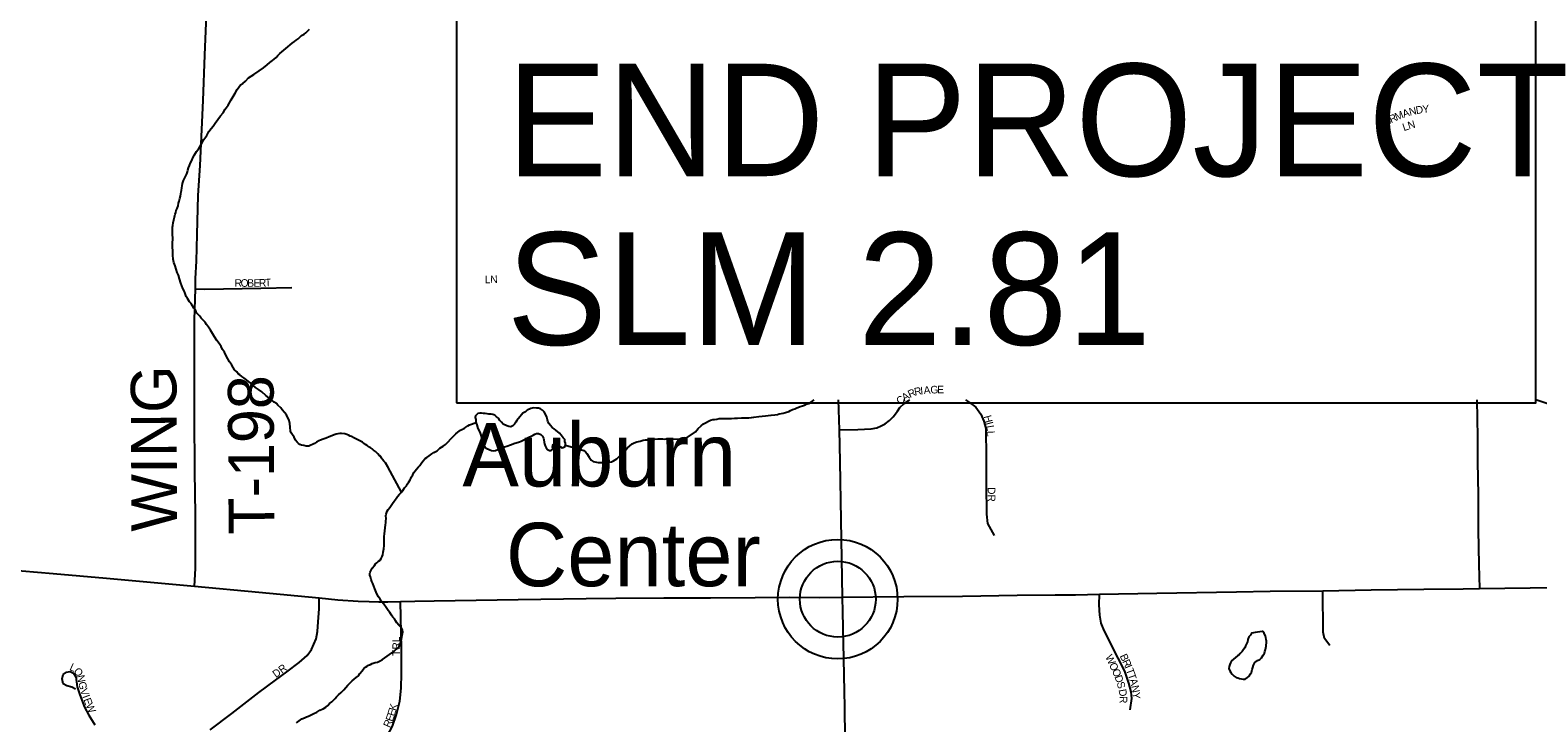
# Model space of a CAD drawing. Extents: x -10.1 to 68, y -9.5 to 29.2.
# Drawn here: x 2.607 to 4.482, y 19.418 to 20.28 of the extents above; entities that cross this region are included whole.
import ezdxf

# ---------------------------------------------------------------- set-up
doc = ezdxf.new("R2010")
doc.units = 0
for name, color, linetype in [('GM_X_County_Road', 7, 'Continuous'), ('GM_X_Minor_Lake', 7, 'Continuous'), ('GM_X_Minor_River', 7, 'Continuous'), ('GM_X_Township_Road', 7, 'Continuous'), ('GM_X_Township_Road_Text', 7, 'Continuous'), ('GM_X_Township_Subdivision', 7, 'Continuous'), ('GM_X_Township_Subdivision_Text', 7, 'Continuous'), ('GM_X_Unincorporated', 7, 'Continuous'), ('GM_X_Unincorporated_Text', 7, 'Continuous'), ('SH_Text', 7, 'Continuous')]:
    doc.layers.add(name, color=color, linetype=linetype)

msp = doc.modelspace()

# ---------------------------------------------------------------- linework, layer by layer
at = {"layer": 'GM_X_County_Road'}
for points in [[(3.6118, 19.82), (3.6127, 19.7829), (3.6136, 19.7433), (3.6149, 19.6704), (3.6165, 19.5745)], [(4.4061, 19.82), (4.4069, 19.7738), (4.4069, 19.743), (4.4076, 19.7017), (4.4079, 19.6581), (4.4086, 19.6153), (4.4092, 19.5855)], [(2.5767, 19.6089), (2.6354, 19.6041), (2.7015, 19.5982), (2.8112, 19.5881), (2.8911, 19.5808), (2.9659, 19.5737), (2.9895, 19.5713), (3.0145, 19.5694), (3.0284, 19.569), (3.0405, 19.5687), (3.0513, 19.5687), (3.0671, 19.5692), (3.0851, 19.5694), (3.1093, 19.5698), (3.2135, 19.5718), (3.2981, 19.5727), (3.335, 19.5733), (3.3949, 19.5737), (3.4527, 19.5735), (3.5085, 19.5739), (3.5513, 19.5743), (3.5884, 19.5741), (3.6165, 19.5745), (3.6934, 19.5753), (3.7664, 19.5759), (3.8343, 19.5769), (3.8817, 19.5774), (3.9069, 19.5776), (3.9366, 19.5781), (4.0079, 19.5793), (4.1072, 19.5811), (4.1489, 19.582), (4.2146, 19.5825), (4.2746, 19.5835), (4.3403, 19.5845), (4.3891, 19.5847), (4.4092, 19.5855), (4.5666, 19.5872)], [(3.6165, 19.5745), (3.6171, 19.5562), (3.6182, 19.4976), (3.619, 19.4571)], [(3.619, 19.4571), (3.6194, 19.4382), (3.62, 19.3984)]]:
    msp.add_lwpolyline(points, dxfattribs=at)
at = {"layer": 'GM_X_Minor_Lake'}
for points in [[(3.2548, 19.757), (3.2571, 19.7593), (3.2563, 19.7616), (3.2571, 19.7646), (3.2594, 19.765), (3.2616, 19.7646), (3.2662, 19.7616), (3.2684, 19.7604), (3.2715, 19.7616), (3.2726, 19.7638), (3.2726, 19.7661), (3.2718, 19.7684), (3.2715, 19.7707), (3.2696, 19.7729), (3.2673, 19.776), (3.265, 19.7786), (3.2605, 19.7824), (3.2582, 19.7839), (3.256, 19.7858), (3.2537, 19.7881), (3.2522, 19.7904), (3.2507, 19.793), (3.2499, 19.7953), (3.2492, 19.7984), (3.2484, 19.8006), (3.2461, 19.8052), (3.2439, 19.8071), (3.2412, 19.809), (3.239, 19.8097), (3.2363, 19.8097), (3.2325, 19.8101), (3.2295, 19.8094), (3.2249, 19.8071), (3.2227, 19.8052), (3.2195, 19.8034)], [(3.209, 19.7897), (3.2068, 19.7878), (3.2045, 19.7866), (3.2022, 19.787), (3.1996, 19.7878), (3.195, 19.79), (3.1928, 19.7923), (3.1909, 19.7946), (3.189, 19.7972), (3.1867, 19.7991), (3.1844, 19.801), (3.1822, 19.8018), (3.1799, 19.8022), (3.1772, 19.8022), (3.175, 19.8026), (3.1727, 19.8033), (3.1704, 19.8033), (3.1682, 19.8037), (3.1659, 19.8037), (3.1636, 19.803), (3.1606, 19.8003), (3.1602, 19.798), (3.161, 19.7957), (3.161, 19.7935), (3.1613, 19.7912), (3.1621, 19.7889), (3.1636, 19.7844), (3.1659, 19.7798), (3.1666, 19.7772), (3.1696, 19.768), (3.1708, 19.7654), (3.1715, 19.7627), (3.1738, 19.7601), (3.1783, 19.7578), (3.1806, 19.757), (3.1829, 19.7567), (3.1855, 19.757), (3.1882, 19.7582), (3.1904, 19.7586), (3.1931, 19.7597), (3.1954, 19.7612), (3.2007, 19.7627), (3.2029, 19.7639), (3.2052, 19.7646), (3.2082, 19.7658), (3.2151, 19.768), (3.2173, 19.7688), (3.22, 19.7699), (3.2253, 19.773), (3.2276, 19.7741), (3.2298, 19.7748), (3.2321, 19.776), (3.2344, 19.7775), (3.2366, 19.7783), (3.2389, 19.7783), (3.2419, 19.7771), (3.2438, 19.7748), (3.245, 19.7726), (3.2457, 19.7703), (3.2461, 19.7676), (3.2465, 19.7654), (3.2472, 19.7627), (3.2484, 19.7604), (3.2503, 19.7581), (3.2525, 19.757), (3.2548, 19.757)], [(3.2195, 19.8034), (3.2177, 19.8014), (3.2158, 19.7991), (3.2121, 19.7946), (3.2109, 19.7923), (3.209, 19.7897)], [(4.1391, 19.5316), (4.1304, 19.5307), (4.1281, 19.5302), (4.1258, 19.5298), (4.1244, 19.5271), (4.1225, 19.5252), (4.1214, 19.5217), (4.1207, 19.5191), (4.1196, 19.5164), (4.1185, 19.5141), (4.1175, 19.5114), (4.116, 19.5095), (4.1141, 19.5068), (4.1115, 19.5044), (4.11, 19.5025), (4.1082, 19.5013), (4.1059, 19.4994), (4.1033, 19.4974), (4.1011, 19.4954), (4.0996, 19.4928), (4.0989, 19.4905), (4.0982, 19.4882), (4.0978, 19.4859), (4.099, 19.4829), (4.1002, 19.4806), (4.1018, 19.4787), (4.1041, 19.4761), (4.1068, 19.4747), (4.1087, 19.474), (4.1107, 19.4732)], [(4.1391, 19.5316), (4.1304, 19.5307), (4.1281, 19.5302), (4.1258, 19.5298), (4.1244, 19.5271), (4.1225, 19.5252), (4.1214, 19.5217), (4.1207, 19.5191), (4.1196, 19.5164), (4.1185, 19.5141), (4.1175, 19.5114), (4.116, 19.5095), (4.1141, 19.5068), (4.1115, 19.5044), (4.11, 19.5025), (4.1082, 19.5013), (4.1059, 19.4994), (4.1033, 19.4974), (4.1011, 19.4954), (4.0996, 19.4928), (4.0989, 19.4905), (4.0982, 19.4882), (4.0978, 19.4859), (4.099, 19.4829), (4.1002, 19.4806), (4.1018, 19.4787), (4.1041, 19.4761), (4.1068, 19.4747), (4.1087, 19.474), (4.1107, 19.4732), (4.1156, 19.4726), (4.1179, 19.4726), (4.1209, 19.4746), (4.1228, 19.4762), (4.1246, 19.4789), (4.1257, 19.4808), (4.1264, 19.4827), (4.1268, 19.4846), (4.1275, 19.4869), (4.1282, 19.49), (4.13, 19.493), (4.1334, 19.4958), (4.136, 19.497), (4.1383, 19.4989), (4.1401, 19.5024), (4.1419, 19.5047), (4.1423, 19.507), (4.143, 19.5093), (4.1437, 19.5116), (4.144, 19.5135), (4.144, 19.5154), (4.1443, 19.5173), (4.1443, 19.5199), (4.1439, 19.5218), (4.1438, 19.5241), (4.143, 19.526), (4.1414, 19.5298), (4.1399, 19.5316), (4.1391, 19.5316)], [(4.1107, 19.4732), (4.1156, 19.4726), (4.1179, 19.4726), (4.1209, 19.4746), (4.1228, 19.4762), (4.1246, 19.4789), (4.1257, 19.4808), (4.1264, 19.4827), (4.1268, 19.4846), (4.1275, 19.4869), (4.1282, 19.49), (4.13, 19.493), (4.1334, 19.4958), (4.136, 19.497), (4.1383, 19.4989), (4.1401, 19.5024), (4.1419, 19.5047), (4.1423, 19.507), (4.143, 19.5093), (4.1437, 19.5116), (4.144, 19.5135), (4.144, 19.5154), (4.1443, 19.5173), (4.1443, 19.5199), (4.1439, 19.5218), (4.1438, 19.5241), (4.143, 19.526), (4.1414, 19.5298), (4.1399, 19.5316), (4.1391, 19.5316)]]:
    msp.add_lwpolyline(points, dxfattribs=at)
at = {"layer": 'GM_X_Minor_River'}
for points in [[(2.8137, 19.9286), (2.8121, 19.932), (2.8102, 19.9342), (2.8067, 19.9399), (2.8047, 19.9421), (2.8035, 19.944), (2.8024, 19.9463), (2.8008, 19.9489), (2.7996, 19.9523), (2.798, 19.9557), (2.7965, 19.9587), (2.7941, 19.9652), (2.7925, 19.9708), (2.7909, 19.9754), (2.7893, 19.9788), (2.7881, 19.9829), (2.7869, 19.9871), (2.7853, 19.9909), (2.7845, 19.995), (2.784, 20), (2.7839, 20.0053), (2.7838, 20.0106), (2.7837, 20.0163), (2.7841, 20.0194), (2.784, 20.0216), (2.7836, 20.0254), (2.7835, 20.0277), (2.7835, 20.03), (2.7835, 20.0323), (2.7838, 20.035), (2.7841, 20.0372), (2.7845, 20.0403), (2.7852, 20.0441), (2.7862, 20.0475), (2.7866, 20.0494), (2.7869, 20.0514), (2.7877, 20.0533), (2.7884, 20.0556), (2.7895, 20.0582), (2.7906, 20.0617), (2.7913, 20.0647), (2.792, 20.0674), (2.7927, 20.0705), (2.7934, 20.0735), (2.7941, 20.0766), (2.7945, 20.0789), (2.7948, 20.0808), (2.7951, 20.0838), (2.7955, 20.0865), (2.7962, 20.0895), (2.7973, 20.093), (2.8013, 20.1014), (2.8024, 20.1041), (2.8027, 20.106), (2.8034, 20.1087), (2.8049, 20.1117), (2.806, 20.1152), (2.8075, 20.1182), (2.8089, 20.1213), (2.8108, 20.1251), (2.8137, 20.129), (2.8163, 20.1328), (2.8193, 20.1378), (2.8226, 20.1443), (2.8263, 20.1493), (2.8289, 20.154), (2.8319, 20.1578), (2.8341, 20.1609), (2.8367, 20.1643), (2.84, 20.169), (2.8434, 20.1736), (2.8467, 20.1774), (2.8493, 20.1817), (2.8527, 20.187), (2.8567, 20.1936), (2.8615, 20.2016), (2.8641, 20.2062), (2.8682, 20.212), (2.8712, 20.214), (2.8746, 20.2167), (2.8783, 20.2209), (2.8847, 20.2252), (2.8914, 20.2295), (2.8967, 20.2334), (2.9012, 20.2369), (2.9049, 20.24), (2.9079, 20.2423), (2.9102, 20.2443), (2.9124, 20.2462), (2.9147, 20.2485), (2.9173, 20.2512), (2.9195, 20.2532), (2.927, 20.2594), (2.93, 20.2621), (2.9326, 20.264), (2.9353, 20.266), (2.9375, 20.2679), (2.9398, 20.2695), (2.942, 20.2714), (2.9443, 20.2737), (2.9476, 20.2753)], [(2.9476, 20.2753), (2.9495, 20.2769), (2.9525, 20.2796), (2.954, 20.2815)], [(3.0684, 19.705), (3.0544, 19.7314), (3.0516, 19.7366), (3.0485, 19.7415), (3.0466, 19.7438), (3.045, 19.7457), (3.0438, 19.7475), (3.0427, 19.7494), (3.0407, 19.7509), (3.0392, 19.7528), (3.0361, 19.7558), (3.0338, 19.7576), (3.0319, 19.7591), (3.0296, 19.7606), (3.0276, 19.7617), (3.0257, 19.7632), (3.0238, 19.7647), (3.0219, 19.7658), (3.02, 19.7673), (3.015, 19.7699), (3.0115, 19.7717), (3.0092, 19.7728), (3.0065, 19.7743), (3.0046, 19.775), (3.0027, 19.7762), (3.0004, 19.7769), (2.9978, 19.7776), (2.9939, 19.7783), (2.9917, 19.7783), (2.9894, 19.7778), (2.9871, 19.7774), (2.9849, 19.7766), (2.9818, 19.7754), (2.9784, 19.7739), (2.9747, 19.7723), (2.9709, 19.7711), (2.9679, 19.7699), (2.9656, 19.7691), (2.9626, 19.7675), (2.9604, 19.7656), (2.9577, 19.7644), (2.9558, 19.7636), (2.9532, 19.7624), (2.9501, 19.7624), (2.9471, 19.7631), (2.944, 19.7638), (2.9421, 19.7645), (2.9402, 19.7656), (2.9387, 19.7675), (2.9367, 19.7701), (2.9348, 19.7735), (2.9328, 19.7765), (2.9313, 19.7792), (2.9305, 19.7811), (2.93, 19.786), (2.9295, 19.7905), (2.9287, 19.7943), (2.9256, 19.8015), (2.9229, 19.8045), (2.9201, 19.8075), (2.9182, 19.8101), (2.9147, 19.8135), (2.9128, 19.8154), (2.9101, 19.8172), (2.907, 19.8195), (2.9036, 19.8224), (2.8997, 19.8254), (2.8947, 19.8299), (2.8905, 19.8329), (2.887, 19.8355), (2.8839, 19.8381), (2.8809, 19.8407), (2.8782, 19.8429), (2.8755, 19.8452), (2.8724, 19.8474), (2.8697, 19.8493), (2.8674, 19.8511), (2.8655, 19.8526), (2.8635, 19.8549), (2.8608, 19.8575), (2.8589, 19.8605), (2.8569, 19.8639), (2.8546, 19.8673), (2.8526, 19.871), (2.8503, 19.8748), (2.8483, 19.8793), (2.846, 19.8827), (2.844, 19.8865), (2.8417, 19.8903), (2.8389, 19.894), (2.8358, 19.8985), (2.8335, 19.9027), (2.8311, 19.9068), (2.8284, 19.9106), (2.8261, 19.914), (2.8241, 19.9166), (2.8218, 19.9192), (2.8195, 19.9218), (2.8176, 19.9241), (2.816, 19.926), (2.8137, 19.9286)], [(3.4213, 19.7717), (3.4342, 19.7804), (3.4376, 19.7843), (3.4413, 19.7878), (3.4443, 19.7902), (3.4466, 19.7913), (3.4503, 19.7937), (3.4529, 19.7949), (3.4556, 19.7957), (3.4579, 19.7958), (3.4609, 19.7962), (3.4636, 19.7967), (3.4658, 19.7967), (3.4738, 19.7969), (3.4761, 19.7969), (3.4788, 19.797), (3.4826, 19.7971), (3.4864, 19.7971), (3.4913, 19.7976), (3.4962, 19.7977), (3.5004, 19.7978), (3.5038, 19.7983), (3.5069, 19.7987), (3.513, 19.7992), (3.5171, 19.7997), (3.5213, 19.8002), (3.5247, 19.8006), (3.5285, 19.8011), (3.5327, 19.8016), (3.5361, 19.802), (3.5384, 19.8025), (3.5406, 19.8029), (3.5433, 19.8037), (3.5463, 19.8045), (3.5501, 19.8058), (3.5524, 19.8069), (3.555, 19.8081), (3.5576, 19.809), (3.5595, 19.8098), (3.5644, 19.8118), (3.5674, 19.8126), (3.5697, 19.8134), (3.572, 19.8146), (3.575, 19.8154), (3.5772, 19.817), (3.5802, 19.8189), (3.5817, 19.82)], [(3.0493, 19.6723), (3.0492, 19.6758), (3.0496, 19.678), (3.0506, 19.6815), (3.0521, 19.6838), (3.054, 19.6861), (3.0555, 19.6884), (3.0573, 19.6911), (3.0595, 19.6942), (3.0618, 19.6973), (3.0636, 19.7), (3.0659, 19.7027), (3.0681, 19.7046), (3.07, 19.7073), (3.0722, 19.7107), (3.0748, 19.7131), (3.0759, 19.7154), (3.0774, 19.7173), (3.0792, 19.7204), (3.0803, 19.7223), (3.0811, 19.7242), (3.0825, 19.7269), (3.084, 19.7296), (3.0855, 19.7319), (3.087, 19.7338), (3.0896, 19.7369), (3.0915, 19.7384), (3.0929, 19.7407), (3.0952, 19.7438), (3.0978, 19.7469), (3.1, 19.7485), (3.1027, 19.7504), (3.1064, 19.7527), (3.1087, 19.7547), (3.1128, 19.7567), (3.1162, 19.7598), (3.1203, 19.7625), (3.1233, 19.7644), (3.1252, 19.7664), (3.1311, 19.7729), (3.1334, 19.7752), (3.136, 19.7776), (3.1386, 19.7799), (3.142, 19.7822), (3.1443, 19.7834), (3.1465, 19.7846), (3.1484, 19.7861), (3.151, 19.7877), (3.1529, 19.7889), (3.1612, 19.792)], [(3.2726, 19.7638), (3.2951, 19.757), (3.2974, 19.7555), (3.299, 19.7532), (3.3021, 19.7487), (3.3044, 19.745), (3.3071, 19.7435), (3.309, 19.7428), (3.3109, 19.7424), (3.3132, 19.7421), (3.3162, 19.7421), (3.3197, 19.7422), (3.3235, 19.7426), (3.3273, 19.7427), (3.3299, 19.7431), (3.3322, 19.7443), (3.3363, 19.7466), (3.3397, 19.7501), (3.3434, 19.754), (3.3471, 19.7575), (3.3498, 19.7602), (3.352, 19.7625), (3.3554, 19.7652), (3.358, 19.7668), (3.3614, 19.768), (3.3652, 19.7688), (3.3693, 19.77), (3.372, 19.7704), (3.3743, 19.7704), (3.3765, 19.7705), (3.38, 19.7705), (3.3838, 19.771), (3.3875, 19.7714), (3.391, 19.7715), (3.3936, 19.7715), (3.3959, 19.7712), (3.3978, 19.7716), (3.4001, 19.7712), (3.4213, 19.7717)], [(2.9377, 19.418), (2.9411, 19.4207), (2.9444, 19.4231), (2.9478, 19.4243), (2.9505, 19.4254), (2.9527, 19.4266), (2.9561, 19.4282), (2.9595, 19.4298), (2.9633, 19.4314), (2.967, 19.4337), (2.9712, 19.4357), (2.9742, 19.4376), (2.9768, 19.4396), (2.9791, 19.4423), (2.9817, 19.4442), (2.9839, 19.4465), (2.9858, 19.4485), (2.9877, 19.4504), (2.9903, 19.4531), (2.9933, 19.4558), (2.9966, 19.4593), (3.0018, 19.4651), (3.0071, 19.4705), (3.0119, 19.4744), (3.0149, 19.4767), (3.0168, 19.4794), (3.0194, 19.4829), (3.0216, 19.4856), (3.0239, 19.4875), (3.0258, 19.4887), (3.0276, 19.4898), (3.0299, 19.4906), (3.0318, 19.4918), (3.0356, 19.493), (3.0386, 19.4938), (3.042, 19.4954), (3.045, 19.497), (3.0476, 19.4989), (3.0506, 19.5009), (3.0536, 19.5032), (3.0566, 19.5051), (3.0585, 19.5063), (3.0611, 19.509), (3.0634, 19.5106), (3.0656, 19.5137), (3.0667, 19.5156), (3.0678, 19.5183), (3.0702, 19.5312), (3.0698, 19.5339), (3.0682, 19.5369), (3.0652, 19.5395), (3.0628, 19.5425), (3.0613, 19.5448), (3.0597, 19.5474), (3.0578, 19.5496), (3.0562, 19.5523), (3.0539, 19.5553), (3.0519, 19.5579), (3.0496, 19.5617), (3.0465, 19.5658), (3.0438, 19.5692), (3.0418, 19.5722), (3.0399, 19.5748), (3.0383, 19.5779), (3.0371, 19.5809), (3.0355, 19.5847), (3.034, 19.5884), (3.0328, 19.5915), (3.0316, 19.5941), (3.0308, 19.5964), (3.03, 19.5998), (3.0292, 19.602), (3.0291, 19.6039), (3.0295, 19.6058), (3.0306, 19.6081), (3.0321, 19.6105), (3.0347, 19.6139), (3.0362, 19.6158), (3.038, 19.6174), (3.0399, 19.6193), (3.0418, 19.6205), (3.0433, 19.6228), (3.0444, 19.6251), (3.0451, 19.6274), (3.0458, 19.6305), (3.0465, 19.6346), (3.0468, 19.6388), (3.0471, 19.6426), (3.0471, 19.6449), (3.047, 19.6472), (3.047, 19.6502), (3.0473, 19.6533), (3.0486, 19.6647), (3.049, 19.667), (3.0489, 19.6689), (3.0493, 19.6723)]]:
    msp.add_lwpolyline(points, dxfattribs=at)
at = {"layer": 'GM_X_Township_Road'}
msp.add_lwpolyline([(2.8112, 19.5881), (2.8121, 19.6103), (2.8121, 19.6398), (2.8121, 19.6777), (2.8114, 19.7303), (2.8109, 19.8009), (2.8109, 19.8396), (2.8112, 19.8952), (2.8112, 19.9195), (2.8121, 19.9582), (2.8124, 19.971), (2.8133, 19.9929), (2.8145, 20.0259), (2.8157, 20.0743), (2.818, 20.1118), (2.8201, 20.1566), (2.8216, 20.1925), (2.8237, 20.2489), (2.826, 20.2993), (2.8277, 20.3501), (2.8293, 20.3976)], dxfattribs=at)
at = {"layer": 'GM_X_Township_Subdivision'}
for points in [[(2.8121, 19.9582), (2.8239, 19.958), (2.8937, 19.9589), (2.9319, 19.96)], [(3.6127, 19.7829), (3.6363, 19.783), (3.6526, 19.784), (3.6598, 19.7854), (3.665, 19.7877), (3.6702, 19.7904), (3.6754, 19.7942), (3.6799, 19.799), (3.6854, 19.806), (3.6882, 19.8105), (3.6938, 19.8155), (3.6995, 19.8193), (3.7006, 19.82)], [(3.7699, 19.82), (3.7751, 19.817), (3.783, 19.8108), (3.7893, 19.8022), (3.7927, 19.7936), (3.7952, 19.7843), (3.7957, 19.748), (3.7959, 19.7143), (3.7961, 19.6778), (3.7975, 19.666), (3.8058, 19.6513)], [(4.2234, 19.5144), (4.2168, 19.523), (4.2148, 19.531), (4.2146, 19.5825)], [(2.8305, 19.4093), (2.8574, 19.4298), (2.8909, 19.4557), (2.9119, 19.4711), (2.9258, 19.4817), (2.9414, 19.4933), (2.9511, 19.502), (2.9565, 19.5095), (2.9596, 19.5159), (2.9622, 19.5227), (2.9638, 19.5319), (2.9648, 19.544), (2.9659, 19.56), (2.9659, 19.5737)], [(2.9501, 19.3199), (2.9461, 19.3083), (2.9438, 19.3029), (2.9409, 19.2998), (2.9371, 19.2982), (2.9322, 19.2993), (2.9289, 19.3026), (2.9279, 19.3076), (2.9294, 19.3133), (2.9369, 19.3182), (2.9511, 19.322), (2.9747, 19.3321), (2.9942, 19.342), (3.0077, 19.3508), (3.0233, 19.364), (3.0372, 19.3793), (3.0468, 19.3944), (3.0572, 19.414), (3.0624, 19.4284), (3.0664, 19.4451), (3.0681, 19.4614), (3.0685, 19.4796), (3.0685, 19.5107), (3.0671, 19.5692)], [(3.9748, 19.4342), (3.9768, 19.4482), (3.976, 19.4565), (3.9733, 19.4673), (3.9682, 19.4825), (3.9601, 19.4987), (3.9427, 19.533), (3.9388, 19.5423), (3.9371, 19.5519), (3.9363, 19.5649), (3.9366, 19.5781)], [(2.663, 19.4602), (2.6585, 19.4623), (2.6522, 19.464), (2.6477, 19.4668), (2.6463, 19.473), (2.6477, 19.4784), (2.6519, 19.4812), (2.6564, 19.4819), (2.6607, 19.48), (2.6635, 19.4753), (2.6651, 19.4628), (2.6685, 19.4529), (2.6743, 19.4376), (2.6795, 19.4277), (2.6871, 19.4156)]]:
    msp.add_lwpolyline(points, dxfattribs=at)
at = {"layer": 'GM_X_Unincorporated'}
for radius in [0.0744, 0.0472]:
    msp.add_circle((3.6112, 19.572), radius, dxfattribs=at)
at = {"layer": 'SH_Text'}
for points in [[(3.137, 19.8164), (4.4795, 19.8164), (4.4795, 20.31), (3.137, 20.31)], [(5.1794, 19.5875), (4.4795, 19.82), (4.4795, 20.31)]]:
    msp.add_lwpolyline(points, close=True, dxfattribs=at)

# ---------------------------------------------------------------- texts
at = {"layer": 'GM_X_Township_Road_Text'}
for s, rotation, p in [('WING', 90.2507, (2.7894, 19.6563)), ('T-198', 90.279, (2.9103, 19.6524))]:
    msp.add_text(s, height=0.05682, rotation=rotation, dxfattribs=at).set_placement(p)
at = {"layer": 'GM_X_Township_Subdivision_Text'}
for s, rotation, p in [('M', 21.4598, (4.3061, 20.1676)), ('A', 18.9187, (4.3153, 20.1712)), ('N', 13.1191, (4.3229, 20.1738)), ('D', 9.2862, (4.3309, 20.1757)), ('Y', 6.5936, (4.339, 20.177)), ('N', 55.5038, (4.2893, 20.1531)), ('O', 38.6188, (4.2935, 20.1594)), ('R', 26.3696, (4.2996, 20.1643)), ('L', 18.3399, (4.3154, 20.1545)), ('N', 15.9874, (4.3216, 20.1566)), ('L', 359.9454, (3.172, 19.9653)), ('N', 2.7735, (3.1791, 19.9653)), ('R', 0.0243, (2.8609, 19.9608)), ('O', 0.0379, (2.8684, 19.9608)), ('B', 0.0243, (2.8767, 19.9608)), ('E', 0.2087, (2.8843, 19.9608)), ('R', 2.1667, (2.8913, 19.9608)), ('T', 3.3048, (2.899, 19.9611)), ('C', 39.532, (3.6886, 19.8134)), ('A', 31.6161, (3.6941, 19.818)), ('R', 25.7505, (3.701, 19.8222)), ('R', 11.5147, (3.7072, 19.8253)), ('I', 5.9976, (3.7143, 19.8267)), ('A', 5.2083, (3.7184, 19.8272)), ('G', 2.1858, (3.7265, 19.8279)), ('E', 0.1093, (3.7348, 19.8282)), ('H', 285.282, (3.7926, 19.7995)), ('I', 285.2666, (3.7948, 19.7914)), ('L', 279.1928, (3.7958, 19.7877)), ('L', 273.007, (3.7969, 19.7813)), ('DR', 270, (3.7977, 19.7115)), ('TRL', 90, (3.0666, 19.5015)), ('W', 295.738, (3.9436, 19.5002)), ('B', 294.3595, (3.9617, 19.5014)), ('L', 335.1581, (2.6548, 19.4843)), ('O', 307.7791, (2.66, 19.4823)), ('DR', 36.2589, (2.9123, 19.4737)), ('O', 295.2453, (3.9483, 19.4904)), ('R', 294.3602, (3.9648, 19.4945)), ('I', 293.3364, (3.9678, 19.4878)), ('T', 289.9901, (3.9694, 19.4841)), ('N', 281.1942, (2.6646, 19.4767)), ('G', 283.1631, (2.6663, 19.4682)), ('O', 293.9736, (3.9519, 19.4829)), ('D', 289.3127, (3.9552, 19.4755)), ('S', 286.5422, (3.9579, 19.4678)), ('T', 288.4263, (3.9717, 19.4779)), ('A', 285.7593, (3.9738, 19.4717)), ('V', 289.1396, (2.6685, 19.459)), ('I', 289.9386, (2.6713, 19.451)), ('E', 289.9038, (2.6727, 19.4471)), ('D', 280.2638, (3.9604, 19.4592)), ('R', 270.4615, (3.9618, 19.4514)), ('N', 281.7514, (3.976, 19.4638)), ('Y', 274.8145, (3.9776, 19.4559)), ('W', 294.8826, (2.6753, 19.44)), ('E', 70.3718, (3.0573, 19.4189)), ('E', 73.3334, (3.0597, 19.4257)), ('K', 76.0766, (3.0618, 19.4325)), ('R', 66.4254, (3.054, 19.4113))]:
    msp.add_text(s, height=0.00947, rotation=rotation, dxfattribs=at).set_placement(p)
at = {"layer": 'GM_X_Unincorporated_Text'}
for s, p in [('Auburn', (3.1442, 19.7123)), ('Center', (3.1984, 19.5881))]:
    msp.add_text(s, height=0.07898, rotation=0, dxfattribs=at).set_placement(p)
at = {"layer": 'SH_Text'}
for s, p in [('END PROJECT', (3.1993, 20.0985)), ('SLM 2.81', (3.1993, 19.8885))]:
    msp.add_text(s, height=0.14, dxfattribs=at).set_placement(p)

doc.saveas('drawing.dxf')
